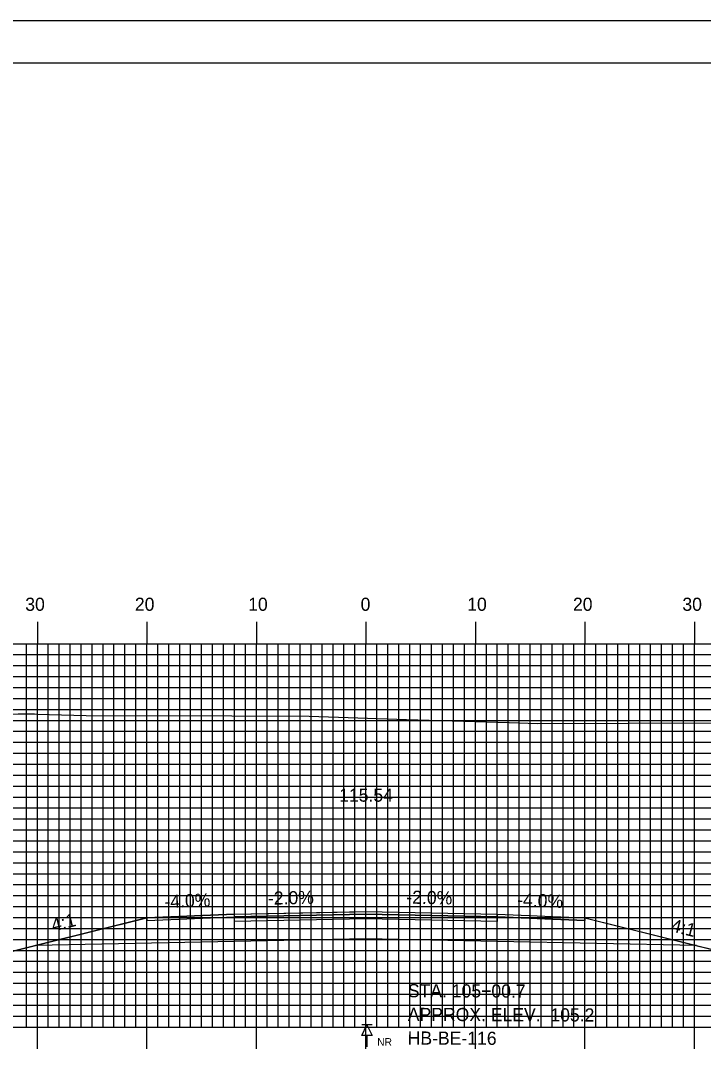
# Model space of a CAD drawing. Extents: x 1767694 to 1768037, y 442591 to 442811.
# Drawn here: x 1767827.9 to 1767890.3, y 442716.2 to 442810.5 of the extents above; entities that cross this region are included whole.
import ezdxf

# ---------------------------------------------------------------- set-up
doc = ezdxf.new("R2010")
doc.units = 0
for name, color, linetype in [('ANNOTATION', 7, 'Continuous'), ('BORDER', 7, 'Continuous'), ('BORING - NO REFUSAL', 7, 'Continuous'), ('D_Roadway_Centerline', 7, 'Continuous'), ('D_Roadway_Centerline_Text', 7, 'Continuous'), ('D_Roadway_Edge_Shoulder', 7, 'Continuous'), ('D_Roadway_Edge_TW', 7, 'Continuous'), ('D_Roadway_Pavement', 7, 'Continuous'), ('D_Roadway_SlopeLines', 7, 'Continuous'), ('D_Roadway_SubGrade', 7, 'Continuous'), ('H_V ANNOTATION', 7, 'Continuous'), ('MAJOR', 7, 'Continuous'), ('MINOR', 7, 'Continuous'), ('PLOT BOUNDARY', 7, 'Continuous'), ('S_Roadway_Centerline', 7, 'Continuous')]:
    doc.layers.add(name, color=color, linetype=linetype)

msp = doc.modelspace()

# ---------------------------------------------------------------- linework, layer by layer
at = {"layer": 'BORDER'}
msp.add_lwpolyline([(1767709.85, 442596.665), (1768029.85, 442596.665), (1768029.85, 442806.665), (1767709.85, 442806.665)], close=True, dxfattribs=at)
at = {"layer": 'BORING - NO REFUSAL'}
for p, q in [((1767860.029, 442718.865), (1767859.07, 442718.865)), ((1767859.55, 442717.906), (1767859.55, 442716.847))]:
    msp.add_line(p, q, dxfattribs=at)
msp.add_lwpolyline([(1767859.55, 442718.865), (1767860.029, 442717.906), (1767859.07, 442717.906)], close=True, dxfattribs=at)
at = {"layer": 'D_Roadway_Centerline'}
msp.add_lwpolyline([(1767825.277, 442725.103), (1767829.276, 442726.102), (1767839.447, 442728.646), (1767839.449, 442728.646), (1767847.448, 442728.966), (1767847.449, 442728.966), (1767858.374, 442729.185), (1767859.449, 442729.206), (1767871.447, 442728.966), (1767871.449, 442728.966), (1767879.448, 442728.646), (1767879.45, 442728.646), (1767889.622, 442726.102), (1767889.623, 442726.102), (1767891.113, 442725.73)], dxfattribs=at)
at = {"layer": 'D_Roadway_Edge_Shoulder'}
for points in [[(1767847.449, 442728.966), (1767839.449, 442728.646), (1767839.449, 442728.396), (1767847.449, 442728.716)], [(1767871.449, 442728.966), (1767879.45, 442728.646), (1767879.45, 442728.396), (1767871.449, 442728.716)]]:
    msp.add_lwpolyline(points, close=True, dxfattribs=at)
at = {"layer": 'D_Roadway_Edge_TW'}
msp.add_lwpolyline([(1767847.449, 442728.716), (1767847.449, 442728.966), (1767859.449, 442729.206), (1767871.449, 442728.966), (1767871.449, 442728.716), (1767859.449, 442728.956)], close=True, dxfattribs=at)
at = {"layer": 'D_Roadway_Pavement'}
msp.add_lwpolyline([(1767847.449, 442728.299), (1767847.449, 442728.716), (1767859.449, 442728.956), (1767871.449, 442728.716), (1767871.449, 442728.299), (1767859.449, 442728.539)], close=True, dxfattribs=at)
at = {"layer": 'D_Roadway_SlopeLines'}
for points in [[(1767839.449, 442728.646), (1767825.276, 442725.102)], [(1767879.45, 442728.646), (1767893.624, 442725.102)]]:
    msp.add_lwpolyline(points, dxfattribs=at)
at = {"layer": 'D_Roadway_SubGrade'}
msp.add_lwpolyline([(1767847.449, 442726.466), (1767829.276, 442726.102), (1767839.449, 442728.646), (1767839.449, 442728.396), (1767847.449, 442728.716), (1767859.449, 442728.956), (1767871.449, 442728.716), (1767879.45, 442728.396), (1767879.45, 442728.646), (1767889.623, 442726.102), (1767871.449, 442726.466), (1767859.449, 442726.706)], close=True, dxfattribs=at)
at = {"layer": 'MAJOR'}
for p, q in [((1767829.45, 442755.669), (1767829.45, 442753.665)), ((1767839.45, 442755.669), (1767839.45, 442753.665)), ((1767849.45, 442755.669), (1767849.45, 442753.665)), ((1767859.45, 442755.669), (1767859.45, 442753.665)), ((1767869.45, 442755.669), (1767869.45, 442753.665)), ((1767879.45, 442755.669), (1767879.45, 442753.665)), ((1767889.45, 442755.669), (1767889.45, 442753.665)), ((1767719.45, 442753.665), (1767999.45, 442753.665)), ((1767719.45, 442753.665), (1767999.45, 442753.665)), ((1767829.45, 442718.665), (1767829.45, 442753.665)), ((1767839.45, 442718.665), (1767839.45, 442753.665)), ((1767849.45, 442718.665), (1767849.45, 442753.665)), ((1767859.45, 442718.665), (1767859.45, 442753.665)), ((1767869.45, 442718.665), (1767869.45, 442753.665)), ((1767879.45, 442718.665), (1767879.45, 442753.665)), ((1767889.45, 442718.665), (1767889.45, 442753.665)), ((1767719.45, 442748.665), (1767999.45, 442748.665)), ((1767719.45, 442743.665), (1767999.45, 442743.665)), ((1767719.45, 442738.665), (1767999.45, 442738.665)), ((1767719.45, 442733.665), (1767999.45, 442733.665)), ((1767719.45, 442728.665), (1767999.45, 442728.665)), ((1767719.45, 442723.665), (1767999.45, 442723.665)), ((1767719.45, 442718.665), (1767999.45, 442718.665)), ((1767719.45, 442718.665), (1767999.45, 442718.665)), ((1767829.45, 442716.661), (1767829.45, 442718.665)), ((1767839.45, 442716.661), (1767839.45, 442718.665)), ((1767849.45, 442716.661), (1767849.45, 442718.665)), ((1767859.45, 442716.661), (1767859.45, 442718.665)), ((1767869.45, 442716.661), (1767869.45, 442718.665)), ((1767879.45, 442716.661), (1767879.45, 442718.665)), ((1767889.45, 442716.661), (1767889.45, 442718.665))]:
    msp.add_line(p, q, dxfattribs=at)
at = {"layer": 'MINOR'}
for p, q in [((1767828.45, 442718.665), (1767828.45, 442753.665)), ((1767830.45, 442718.665), (1767830.45, 442753.665)), ((1767831.45, 442718.665), (1767831.45, 442753.665)), ((1767832.45, 442718.665), (1767832.45, 442753.665)), ((1767833.45, 442718.665), (1767833.45, 442753.665)), ((1767834.45, 442718.665), (1767834.45, 442753.665)), ((1767835.45, 442718.665), (1767835.45, 442753.665)), ((1767836.45, 442718.665), (1767836.45, 442753.665)), ((1767837.45, 442718.665), (1767837.45, 442753.665)), ((1767838.45, 442718.665), (1767838.45, 442753.665)), ((1767840.45, 442718.665), (1767840.45, 442753.665)), ((1767841.45, 442718.665), (1767841.45, 442753.665)), ((1767842.45, 442718.665), (1767842.45, 442753.665)), ((1767843.45, 442718.665), (1767843.45, 442753.665)), ((1767844.45, 442718.665), (1767844.45, 442753.665)), ((1767845.45, 442718.665), (1767845.45, 442753.665)), ((1767846.45, 442718.665), (1767846.45, 442753.665)), ((1767847.45, 442718.665), (1767847.45, 442753.665)), ((1767848.45, 442718.665), (1767848.45, 442753.665)), ((1767850.45, 442718.665), (1767850.45, 442753.665)), ((1767851.45, 442718.665), (1767851.45, 442753.665)), ((1767852.45, 442718.665), (1767852.45, 442753.665)), ((1767853.45, 442718.665), (1767853.45, 442753.665)), ((1767854.45, 442718.665), (1767854.45, 442753.665)), ((1767855.45, 442718.665), (1767855.45, 442753.665)), ((1767856.45, 442718.665), (1767856.45, 442753.665)), ((1767857.45, 442718.665), (1767857.45, 442753.665)), ((1767858.45, 442718.665), (1767858.45, 442753.665)), ((1767860.45, 442718.665), (1767860.45, 442753.665)), ((1767861.45, 442718.665), (1767861.45, 442753.665)), ((1767862.45, 442718.665), (1767862.45, 442753.665)), ((1767863.45, 442718.665), (1767863.45, 442753.665)), ((1767864.45, 442718.665), (1767864.45, 442753.665)), ((1767865.45, 442718.665), (1767865.45, 442753.665)), ((1767866.45, 442718.665), (1767866.45, 442753.665)), ((1767867.45, 442718.665), (1767867.45, 442753.665)), ((1767868.45, 442718.665), (1767868.45, 442753.665)), ((1767870.45, 442718.665), (1767870.45, 442753.665)), ((1767871.45, 442718.665), (1767871.45, 442753.665)), ((1767872.45, 442718.665), (1767872.45, 442753.665)), ((1767873.45, 442718.665), (1767873.45, 442753.665)), ((1767874.45, 442718.665), (1767874.45, 442753.665)), ((1767875.45, 442718.665), (1767875.45, 442753.665)), ((1767876.45, 442718.665), (1767876.45, 442753.665)), ((1767877.45, 442718.665), (1767877.45, 442753.665)), ((1767878.45, 442718.665), (1767878.45, 442753.665)), ((1767880.45, 442718.665), (1767880.45, 442753.665)), ((1767881.45, 442718.665), (1767881.45, 442753.665)), ((1767882.45, 442718.665), (1767882.45, 442753.665)), ((1767883.45, 442718.665), (1767883.45, 442753.665)), ((1767884.45, 442718.665), (1767884.45, 442753.665)), ((1767885.45, 442718.665), (1767885.45, 442753.665)), ((1767886.45, 442718.665), (1767886.45, 442753.665)), ((1767887.45, 442718.665), (1767887.45, 442753.665)), ((1767888.45, 442718.665), (1767888.45, 442753.665)), ((1767719.45, 442752.665), (1767999.45, 442752.665)), ((1767719.45, 442751.665), (1767999.45, 442751.665)), ((1767719.45, 442750.665), (1767999.45, 442750.665)), ((1767719.45, 442749.665), (1767999.45, 442749.665)), ((1767719.45, 442747.665), (1767999.45, 442747.665)), ((1767719.45, 442746.665), (1767999.45, 442746.665)), ((1767719.45, 442745.665), (1767999.45, 442745.665)), ((1767719.45, 442744.665), (1767999.45, 442744.665)), ((1767719.45, 442742.665), (1767999.45, 442742.665)), ((1767719.45, 442741.665), (1767999.45, 442741.665)), ((1767719.45, 442740.665), (1767999.45, 442740.665)), ((1767719.45, 442739.665), (1767999.45, 442739.665)), ((1767719.45, 442737.665), (1767999.45, 442737.665)), ((1767719.45, 442736.665), (1767999.45, 442736.665)), ((1767719.45, 442735.665), (1767999.45, 442735.665)), ((1767719.45, 442734.665), (1767999.45, 442734.665)), ((1767719.45, 442732.665), (1767999.45, 442732.665)), ((1767719.45, 442731.665), (1767999.45, 442731.665)), ((1767719.45, 442730.665), (1767999.45, 442730.665)), ((1767719.45, 442729.665), (1767999.45, 442729.665)), ((1767719.45, 442727.665), (1767999.45, 442727.665)), ((1767719.45, 442726.665), (1767999.45, 442726.665)), ((1767719.45, 442725.665), (1767999.45, 442725.665)), ((1767719.45, 442724.665), (1767999.45, 442724.665)), ((1767719.45, 442722.665), (1767999.45, 442722.665)), ((1767719.45, 442721.665), (1767999.45, 442721.665)), ((1767719.45, 442720.665), (1767999.45, 442720.665)), ((1767719.45, 442719.665), (1767999.45, 442719.665))]:
    msp.add_line(p, q, dxfattribs=at)
at = {"layer": 'PLOT BOUNDARY'}
msp.add_lwpolyline([(1767693.663, 442590.547), (1768033.663, 442590.547), (1768033.663, 442810.547), (1767693.663, 442810.547)], close=True, dxfattribs=at)
at = {"layer": 'S_Roadway_Centerline'}
msp.add_lwpolyline([(1767768.075, 442747.158), (1767777.122, 442747.25), (1767784.504, 442747.274), (1767796.068, 442747.273), (1767803.561, 442747.18), (1767810.37, 442747.172), (1767810.51, 442747.219), (1767815.229, 442747.02), (1767815.429, 442747.018), (1767827.696, 442747.245), (1767829.183, 442747.258), (1767829.413, 442747.24), (1767833.919, 442747.097), (1767847.208, 442747.09), (1767854.272, 442747.05), (1767863.171, 442746.755), (1767872.529, 442746.462), (1767875.146, 442746.389), (1767891.751, 442746.451)], dxfattribs=at)

# ---------------------------------------------------------------- texts
at = {"layer": 'ANNOTATION'}
for s, rotation, p in [('-2.0%', 1.14576, (1767850.518, 442729.828)), ('-2.0%', 358.85424, (1767863.134, 442729.933)), ('-4.0%', 2.29052, (1767841.08, 442729.513)), ('-4.0%', 357.70948, (1767873.24, 442729.696)), ('4:1', 14.03888, (1767830.898, 442727.37)), ('4:1', 345.96047, (1767887.234, 442727.412))]:
    msp.add_text(s, height=1.2, rotation=rotation, dxfattribs=at).set_placement(p)
at = {"layer": 'BORING - NO REFUSAL'}
for s, p in [('STA. 105+00.7', (1767863.28, 442721.382)), ('APPROX. ELEV.  105.2', (1767863.273, 442719.222)), ('HB-BE-116', (1767863.266, 442717.062))]:
    msp.add_text(s, height=1.2, rotation=359.81416, dxfattribs=at).set_placement(p)
msp.add_text('NR', height=0.6998, dxfattribs=at).set_placement((1767860.482, 442716.95))
at = {"layer": 'D_Roadway_Centerline'}
for s, p in [('C', (1767859.444, 442729.206)), ('L', (1767859.449, 442729.199))]:
    msp.add_text(s, height=0.0146, dxfattribs=at).set_placement(p)
at = {"layer": 'D_Roadway_Centerline_Text'}
msp.add_text('115.54', height=1.2, dxfattribs=at).set_placement((1767857.009, 442739.236))
at = {"layer": 'H_V ANNOTATION'}
for s, p in [('30', (1767828.347, 442756.665)), ('20', (1767838.357, 442756.665)), ('10', (1767848.7, 442756.665)), ('0', (1767858.968, 442756.665)), ('10', (1767868.7, 442756.665)), ('20', (1767878.357, 442756.665)), ('30', (1767888.347, 442756.665))]:
    msp.add_text(s, height=1.2, dxfattribs=at).set_placement(p)

doc.saveas('drawing.dxf')
